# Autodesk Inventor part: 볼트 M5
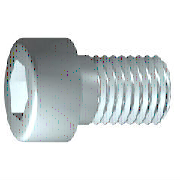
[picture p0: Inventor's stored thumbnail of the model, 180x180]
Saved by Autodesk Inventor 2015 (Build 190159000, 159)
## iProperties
IsCustomPart: 1
Created: 2012-02
Part Number: 볼트 M5
Material: 강철, 연강
Description: 6각머리 태핑 나사
Document SubType Name: Modeling
Standard: KS B 1003
Designer: mduedu
Standards Organization: KS
Language: ko-KR
Size Designation: M 5 x 16
Categories: <MemberInstance><Categories><Category DisplayName="조임쇠" InternalName="e4da775c-781d-43d5-af7c-5136215cf5a6" Mnemonic="FSTN"><Category DisplayName="볼트" InternalN
Density: 1 g/cm^3
Appearance: 강철
Author: mduedu
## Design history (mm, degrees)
sketch "스케치1"
  geometry: L1 (-1.167, 0)-(16, 0); L2 (16, 0)-(16, 2.5); L3 (16, 2.5)-(2, 2.5); L4 (2, 2.5)-(1.509, 2.5); L5 (1.509, 2.5)-(0, 2.5); L6 (0, 2.5)-(0, 4.25); L7 (0, 4.25)-(-5, 4.25); L8 (-5, 4.25)-(-5, 2.309); L9 (-5, 2.309)-(-2.5, 2.309); L10 (-2.5, 2.309)-(-1.167, 0); L11 (-9.2, 0)-(20.2, 0) reference; L12 (0, -0.85)-(0, 5.1) reference; L13 (2, 2.5)-(0, 2.5)
  constraints: 22 end point, 6 parallel, 2 collinear, 2 perpendicular, 1 horizontal, 1 point on line
  dimensions: "d1" = 14 distance from line of L3.end L2 (= GEL); "d2" = 0.49086 distance of L4.end L3.end (computed from GAL); "d3" = 5 distance between parallel lines of L8 L6 (= KOH); "d4" = 2.5 distance of L8.end L9.end (= INTI); "d5" = 60 deg angle of L10 L1; "d6" = 5 diameter of L3 L1 (= GD); "d7" = 5 diameter of L5 L1 (= BDM); "d8" = 4.6188 diameter of L9 L1 (= 1.1547 x SW); "d9" = 8.5 diameter of L7 L1 (= KOD); "d26" = 16 distance between parallel lines of L12 L2 (= NLG)
revolve "본체" sketch "스케치1" stored, may be unused: angle "d10" = 90 deg
sketch "스케치2"
  geometry: L1 (0, -5.95)-(0, 5.95) reference; L2 (-5.95, 0)-(5.95, 0) reference; L3 (2.309, 0)-(1.155, -2); L4 (1.155, -2)-(-1.155, -2); L5 (-1.155, -2)-(-2.309, 0); L6 (-2.309, 0)-(-1.155, 2); L7 (-1.155, 2)-(1.155, 2); L8 (1.155, 2)-(2.309, 0); 2 further points
  constraints: 12 end point, 1 coincident, 1 horizontal alignment, 1 point on line, 12 other
extrude "슬롯" join sketch "스케치2" stored distance "d11" = 10; taper "d12" = 0 deg
workplane "Work Plane1"
fillet "Fillet2" dims "d30" = 0.1 (= R)
body "Solid1"
fillet "모깎기1" dims "d17" = 0.5 (= RR)
feature "스레드" dims "d13" = 14 (= GEL), "d14" = 0
chamfer "모따기1" distance "d15" = 0.49076 (= -0.5 x SPD + 0.5 x GD); stored, may be unused: second distance "d16" = 0.49076 (= GUL), angle "d27" = 45 deg
other parameters: "GD" = 5 (= NND) [user parameter; used in 2 equation terms], "NLG" = 16 [user parameter; used in 1 equation term], "GEL" = 14 [user parameter; used in 2 equation terms], "KOD" = 8.5 [user parameter; used in 1 equation term], "KOH" = 5 [user parameter; used in 1 equation term], "INTI" = 2.5 [user parameter; used in 1 equation term], "GAL" = 0.49076 (= 0.61345 x PTC) [user parameter; used in 1 equation term], "GUL" = 0.49076 (= 0.61345 x PTC) [user parameter; used in 1 equation term], "BDM" = 5 (= NND) [user parameter; used in 1 equation term], "SW" = 4 [user parameter; used in 2 equation terms], "RR" = 0.5 [user parameter; used in 1 equation term], "SPD" = 4.01848 (= NND - 1.2269 x PTC) [user parameter; used in 1 equation term], "d19" = 0, "d28" = 0, "d29" = 0, "R" = 0.1 [user parameter; used in 1 equation term], "PHH" = 0.2 [user parameter], "GD1" = 4.01848 (= THREADDIA - 1.2269 x PTC) [user parameter], "THREADDIA" = 5 [user parameter; used in 1 equation term], "FAWI" = 45 deg [user parameter], "TPU" = 12.5 (computed from PTC) [user parameter], "PTC" = 0.8 [user parameter; used in 5 equation terms], "NND" = 5 [user parameter; used in 3 equation terms], "TOA" = 30 deg [user parameter], "E0" = 4.62 (= 1.155 x SW) [user parameter]
